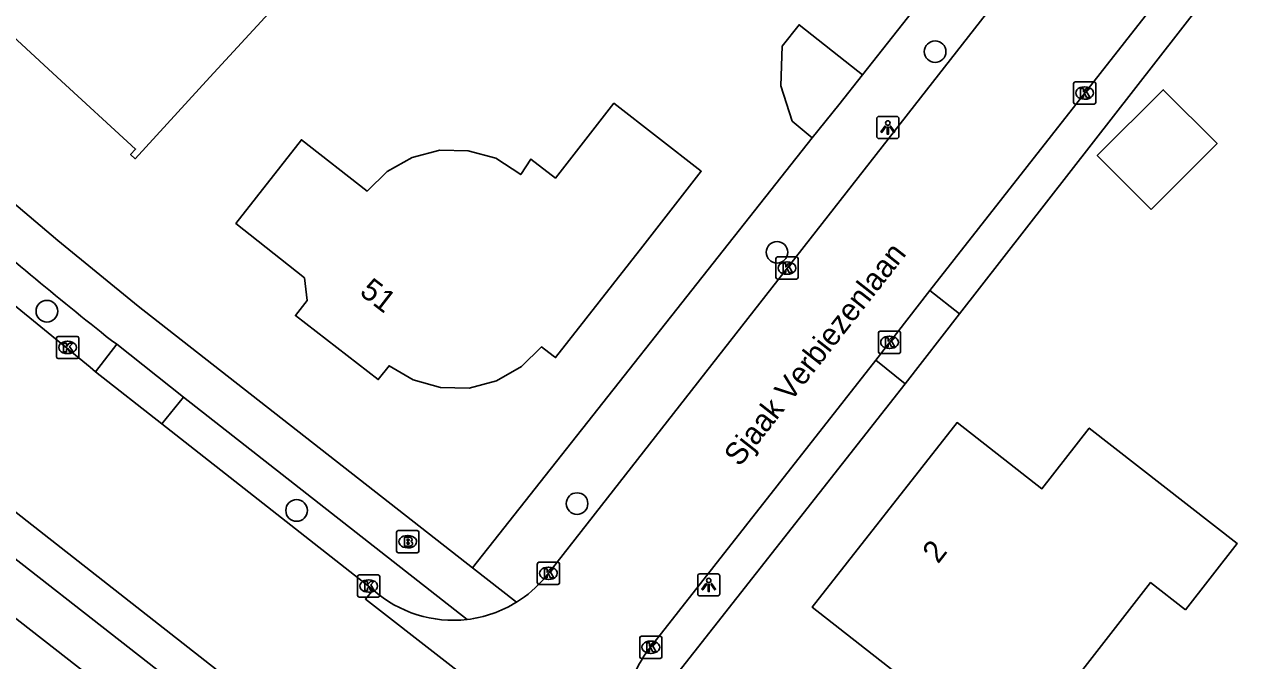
# Model space of a CAD drawing. Extents: x 157321 to 158827, y 386650 to 388532.
# Drawn here: x 158051 to 158106.5, y 387216.4 to 387245.2 of the extents above; entities that cross this region are included whole.
import ezdxf

# ---------------------------------------------------------------- set-up
doc = ezdxf.new("R2010")
doc.units = 0
for name, color, linetype in [('IMGEO_Boom', 7, 'Continuous'), ('IMGEO_Brandkraan', 7, 'Continuous'), ('IMGEO_Groenvoorziening', 7, 'Continuous'), ('IMGEO_Kolk', 7, 'Continuous'), ('IMGEO_Lichtpunt', 7, 'Continuous'), ('IMGEO_Openbare_ruimte_label', 7, 'Continuous'), ('IMGEO_Pand', 7, 'Continuous'), ('IMGEO_Pand_nummerreeks', 7, 'Continuous'), ('IMGEO_Rijbaan_lokaal_gesloten', 7, 'Continuous'), ('IMGEO_Voetpad_open', 7, 'Continuous')]:
    doc.layers.add(name, color=color, linetype=linetype)

msp = doc.modelspace()

# ---------------------------------------------------------------- linework, layer by layer
at = {"layer": 'IMGEO_Boom'}
for centre in [(158092.082, 387243.962), (158084.941, 387234.894), (158051.968, 387232.233), (158063.245, 387223.227), (158075.91, 387223.537)]:
    msp.add_circle(centre, 0.489, dxfattribs=at)
at = {"layer": 'IMGEO_Brandkraan'}
for p, q in [((158067.763, 387221.39), (158067.763, 387222.242)), ((158067.838, 387222.316), (158068.69, 387222.316)), ((158068.251, 387222.096), (158068.276, 387222.096)), ((158068.764, 387222.242), (158068.764, 387221.39)), ((158068.274, 387221.536), (158068.249, 387221.536)), ((158068.69, 387221.316), (158067.838, 387221.316))]:
    msp.add_line(p, q, dxfattribs=at)
for points in [[(158067.763, 387221.39), (158067.763, 387222.242)], [(158067.838, 387222.316), (158068.69, 387222.316)], [(158068.111, 387222.016), (158068.111, 387221.616), (158068.324, 387221.616)], [(158068.342, 387222.016), (158068.111, 387222.016)], [(158068.29, 387221.935), (158068.236, 387221.935), (158068.236, 387221.859)], [(158068.764, 387222.242), (158068.764, 387221.39)], [(158068.236, 387221.859), (158068.289, 387221.859)], [(158068.298, 387221.783), (158068.236, 387221.783), (158068.236, 387221.702)], [(158068.236, 387221.702), (158068.298, 387221.702)], [(158068.69, 387221.316), (158067.838, 387221.316)]]:
    msp.add_lwpolyline(points, dxfattribs=at)
for centre, radius, start, end in [((158067.84, 387222.24), 0.0765, 91.552, 178.448), ((158067.84, 387222.24), 0.0765, 91.552, 178.448), ((158068.291, 387221.897), 0.0379, 267.8285, 90.9355), ((158068.346, 387221.871), 0.145, 59.4692, 91.5367), ((158068.371, 387221.918), 0.0922, 285.5137, 58.1501), ((158068.688, 387222.24), 0.0765, 1.552, 88.448), ((158068.688, 387222.24), 0.0765, 1.552, 88.448), ((158067.84, 387221.392), 0.0765, 181.552, 268.448), ((158067.84, 387221.392), 0.0765, 181.552, 268.448), ((158068.299, 387221.742), 0.0404, 269.8759, 90.5077), ((158068.33, 387221.867), 0.251, 268.6676, 293.5347), ((158068.376, 387221.726), 0.105, 301.3115, 78.989), ((158068.688, 387221.392), 0.0765, 271.552, 358.448), ((158068.688, 387221.392), 0.0765, 271.552, 358.448)]:
    msp.add_arc(centre, radius, start, end, dxfattribs=at)
for centre, major_axis, ratio, start_param, end_param in [((158068.25, 387221.816), (-0.387, 0.002), 0.722429, 4.712389, 7.853982), ((158068.275, 387221.816), (-0.39, 0.002), 0.717154, 1.570796, 4.712389)]:
    msp.add_ellipse(centre, major_axis=major_axis, ratio=ratio, start_param=start_param, end_param=end_param, dxfattribs=at)
at = {"layer": 'IMGEO_Groenvoorziening'}
for points in [[(158088.804, 387242.909), (158103.97, 387262.173)], [(158112.253, 387256.634), (158107.095, 387250), (158093.185, 387232.11)], [(158071.192, 387220.632), (158086.535, 387240.062)], [(158090.73, 387228.956), (158079.248, 387214.335)]]:
    msp.add_lwpolyline(points, dxfattribs=at)
at = {"layer": 'IMGEO_Kolk'}
for p, q in [((158098.333, 387241.667), (158098.333, 387242.519)), ((158098.408, 387242.593), (158099.26, 387242.593)), ((158099.334, 387242.519), (158099.334, 387241.667)), ((158098.821, 387242.373), (158098.846, 387242.373)), ((158099.26, 387241.593), (158098.408, 387241.593)), ((158098.844, 387241.813), (158098.819, 387241.813)), ((158084.967, 387234.683), (158085.819, 387234.683)), ((158084.892, 387233.757), (158084.892, 387234.609)), ((158085.38, 387234.463), (158085.405, 387234.463)), ((158085.893, 387234.609), (158085.893, 387233.757)), ((158085.819, 387233.683), (158084.967, 387233.683)), ((158085.403, 387233.903), (158085.378, 387233.903)), ((158089.599, 387231.326), (158090.451, 387231.326)), ((158052.401, 387230.168), (158052.401, 387231.02)), ((158052.476, 387231.094), (158053.328, 387231.094)), ((158052.889, 387230.874), (158052.914, 387230.874)), ((158053.402, 387231.02), (158053.402, 387230.168)), ((158089.524, 387230.4), (158089.524, 387231.252)), ((158090.012, 387231.106), (158090.037, 387231.106)), ((158090.525, 387231.252), (158090.525, 387230.4)), ((158052.912, 387230.314), (158052.887, 387230.314)), ((158090.451, 387230.326), (158089.599, 387230.326)), ((158090.035, 387230.546), (158090.01, 387230.546)), ((158053.328, 387230.094), (158052.476, 387230.094)), ((158074.116, 387219.96), (158074.116, 387220.812)), ((158074.191, 387220.886), (158075.043, 387220.886)), ((158075.117, 387220.812), (158075.117, 387219.96)), ((158066.001, 387219.387), (158066.001, 387220.239)), ((158066.076, 387220.313), (158066.928, 387220.313)), ((158067.002, 387220.239), (158067.002, 387219.387)), ((158074.604, 387220.666), (158074.629, 387220.666)), ((158066.489, 387220.093), (158066.514, 387220.093)), ((158075.043, 387219.886), (158074.191, 387219.886)), ((158074.627, 387220.106), (158074.602, 387220.106)), ((158066.928, 387219.313), (158066.076, 387219.313)), ((158066.512, 387219.533), (158066.487, 387219.533)), ((158078.74, 387216.618), (158078.74, 387217.47)), ((158078.815, 387217.544), (158079.667, 387217.544)), ((158079.741, 387217.47), (158079.741, 387216.618)), ((158079.228, 387217.324), (158079.253, 387217.324)), ((158079.667, 387216.544), (158078.815, 387216.544)), ((158079.251, 387216.764), (158079.226, 387216.764))]:
    msp.add_line(p, q, dxfattribs=at)
for points in [[(158098.333, 387241.667), (158098.333, 387242.519)], [(158098.408, 387242.593), (158099.26, 387242.593)], [(158099.334, 387242.519), (158099.334, 387241.667)], [(158098.654, 387242.293), (158098.777, 387242.293), (158098.777, 387242.142), (158098.907, 387242.293), (158099.071, 387242.293), (158098.925, 387242.142), (158099.078, 387241.893), (158098.926, 387241.893), (158098.841, 387242.057), (158098.777, 387241.99), (158098.777, 387241.893), (158098.654, 387241.893), (158098.654, 387242.293)], [(158099.26, 387241.593), (158098.408, 387241.593)], [(158084.967, 387234.683), (158085.819, 387234.683)], [(158084.892, 387233.757), (158084.892, 387234.609)], [(158085.213, 387234.383), (158085.336, 387234.383), (158085.336, 387234.232), (158085.466, 387234.383), (158085.63, 387234.383), (158085.484, 387234.232), (158085.637, 387233.983), (158085.485, 387233.983), (158085.4, 387234.147), (158085.336, 387234.08), (158085.336, 387233.983), (158085.213, 387233.983), (158085.213, 387234.383)], [(158085.893, 387234.609), (158085.893, 387233.757)], [(158085.819, 387233.683), (158084.967, 387233.683)], [(158089.599, 387231.326), (158090.451, 387231.326)], [(158052.401, 387230.168), (158052.401, 387231.02)], [(158052.476, 387231.094), (158053.328, 387231.094)], [(158052.722, 387230.794), (158052.845, 387230.794), (158052.845, 387230.643), (158052.975, 387230.794), (158053.139, 387230.794), (158052.993, 387230.643), (158053.146, 387230.394), (158052.994, 387230.394), (158052.909, 387230.558), (158052.845, 387230.491), (158052.845, 387230.394), (158052.722, 387230.394), (158052.722, 387230.794)], [(158053.402, 387231.02), (158053.402, 387230.168)], [(158089.524, 387230.4), (158089.524, 387231.252)], [(158089.845, 387231.026), (158089.968, 387231.026), (158089.968, 387230.875), (158090.098, 387231.026), (158090.262, 387231.026), (158090.116, 387230.875), (158090.269, 387230.626), (158090.117, 387230.626), (158090.032, 387230.79), (158089.968, 387230.723), (158089.968, 387230.626), (158089.845, 387230.626), (158089.845, 387231.026)], [(158090.525, 387231.252), (158090.525, 387230.4)], [(158090.451, 387230.326), (158089.599, 387230.326)], [(158053.328, 387230.094), (158052.476, 387230.094)], [(158074.116, 387219.96), (158074.116, 387220.812)], [(158074.191, 387220.886), (158075.043, 387220.886)], [(158075.117, 387220.812), (158075.117, 387219.96)], [(158066.001, 387219.387), (158066.001, 387220.239)], [(158066.076, 387220.313), (158066.928, 387220.313)], [(158067.002, 387220.239), (158067.002, 387219.387)], [(158074.437, 387220.586), (158074.56, 387220.586), (158074.56, 387220.435), (158074.69, 387220.586), (158074.854, 387220.586), (158074.708, 387220.435), (158074.861, 387220.186), (158074.709, 387220.186), (158074.624, 387220.35), (158074.56, 387220.283), (158074.56, 387220.186), (158074.437, 387220.186), (158074.437, 387220.586)], [(158066.322, 387220.013), (158066.445, 387220.013), (158066.445, 387219.862), (158066.575, 387220.013), (158066.739, 387220.013), (158066.593, 387219.862), (158066.746, 387219.613), (158066.594, 387219.613), (158066.509, 387219.777), (158066.445, 387219.71), (158066.445, 387219.613), (158066.322, 387219.613), (158066.322, 387220.013)], [(158075.043, 387219.886), (158074.191, 387219.886)], [(158066.928, 387219.313), (158066.076, 387219.313)], [(158078.74, 387216.618), (158078.74, 387217.47)], [(158078.815, 387217.544), (158079.667, 387217.544)], [(158079.741, 387217.47), (158079.741, 387216.618)], [(158079.061, 387217.244), (158079.184, 387217.244), (158079.184, 387217.093), (158079.314, 387217.244), (158079.478, 387217.244), (158079.332, 387217.093), (158079.485, 387216.844), (158079.333, 387216.844), (158079.248, 387217.008), (158079.184, 387216.941), (158079.184, 387216.844), (158079.061, 387216.844), (158079.061, 387217.244)], [(158079.667, 387216.544), (158078.815, 387216.544)]]:
    msp.add_lwpolyline(points, dxfattribs=at)
for centre, start, end in [((158098.41, 387242.517), 91.552, 178.448), ((158098.41, 387242.517), 91.552, 178.448), ((158099.258, 387242.517), 1.552, 88.448), ((158099.258, 387242.517), 1.552, 88.448), ((158098.41, 387241.669), 181.552, 268.448), ((158098.41, 387241.669), 181.552, 268.448), ((158099.258, 387241.669), 271.552, 358.448), ((158099.258, 387241.669), 271.552, 358.448), ((158084.969, 387234.607), 91.552, 178.448), ((158084.969, 387234.607), 91.552, 178.448), ((158085.817, 387234.607), 1.552, 88.448), ((158085.817, 387234.607), 1.552, 88.448), ((158084.969, 387233.759), 181.552, 268.448), ((158084.969, 387233.759), 181.552, 268.448), ((158085.817, 387233.759), 271.552, 358.448), ((158085.817, 387233.759), 271.552, 358.448), ((158089.601, 387231.25), 91.552, 178.448), ((158089.601, 387231.25), 91.552, 178.448), ((158090.449, 387231.25), 1.552, 88.448), ((158090.449, 387231.25), 1.552, 88.448), ((158052.478, 387231.018), 91.552, 178.448), ((158052.478, 387231.018), 91.552, 178.448), ((158053.326, 387231.018), 1.552, 88.448), ((158053.326, 387231.018), 1.552, 88.448), ((158089.601, 387230.402), 181.552, 268.448), ((158089.601, 387230.402), 181.552, 268.448), ((158090.449, 387230.402), 271.552, 358.448), ((158090.449, 387230.402), 271.552, 358.448), ((158052.478, 387230.17), 181.552, 268.448), ((158052.478, 387230.17), 181.552, 268.448), ((158053.326, 387230.17), 271.552, 358.448), ((158053.326, 387230.17), 271.552, 358.448), ((158074.193, 387220.81), 91.552, 178.448), ((158074.193, 387220.81), 91.552, 178.448), ((158075.041, 387220.81), 1.552, 88.448), ((158075.041, 387220.81), 1.552, 88.448), ((158066.078, 387220.237), 91.552, 178.448), ((158066.078, 387220.237), 91.552, 178.448), ((158066.926, 387220.237), 1.552, 88.448), ((158066.926, 387220.237), 1.552, 88.448), ((158074.193, 387219.962), 181.552, 268.448), ((158074.193, 387219.962), 181.552, 268.448), ((158075.041, 387219.962), 271.552, 358.448), ((158075.041, 387219.962), 271.552, 358.448), ((158066.078, 387219.389), 181.552, 268.448), ((158066.078, 387219.389), 181.552, 268.448), ((158066.926, 387219.389), 271.552, 358.448), ((158066.926, 387219.389), 271.552, 358.448), ((158078.817, 387217.468), 91.552, 178.448), ((158078.817, 387217.468), 91.552, 178.448), ((158079.665, 387217.468), 1.552, 88.448), ((158079.665, 387217.468), 1.552, 88.448), ((158078.817, 387216.62), 181.552, 268.448), ((158078.817, 387216.62), 181.552, 268.448), ((158079.665, 387216.62), 271.552, 358.448), ((158079.665, 387216.62), 271.552, 358.448)]:
    msp.add_arc(centre, 0.0765, start, end, dxfattribs=at)
for centre, major_axis, ratio, start_param, end_param in [((158098.82, 387242.093), (-0.387, 0.002), 0.722429, 4.712389, 7.853982), ((158098.845, 387242.093), (-0.39, 0.002), 0.717154, 1.570796, 4.712389), ((158085.379, 387234.183), (-0.387, 0.002), 0.722429, 4.712389, 7.853982), ((158085.404, 387234.183), (-0.39, 0.002), 0.717154, 1.570796, 4.712389), ((158052.888, 387230.594), (-0.387, 0.002), 0.722429, 4.712389, 7.853982), ((158052.913, 387230.594), (-0.39, 0.002), 0.717154, 1.570796, 4.712389), ((158090.011, 387230.826), (-0.387, 0.002), 0.722429, 4.712389, 7.853982), ((158090.036, 387230.826), (-0.39, 0.002), 0.717154, 1.570796, 4.712389), ((158074.603, 387220.386), (-0.387, 0.002), 0.722429, 4.712389, 7.853982), ((158074.628, 387220.386), (-0.39, 0.002), 0.717154, 1.570796, 4.712389), ((158066.488, 387219.813), (-0.387, 0.002), 0.722429, 4.712389, 7.853982), ((158066.513, 387219.813), (-0.39, 0.002), 0.717154, 1.570796, 4.712389), ((158079.227, 387217.044), (-0.387, 0.002), 0.722429, 4.712389, 7.853982), ((158079.252, 387217.044), (-0.39, 0.002), 0.717154, 1.570796, 4.712389)]:
    msp.add_ellipse(centre, major_axis=major_axis, ratio=ratio, start_param=start_param, end_param=end_param, dxfattribs=at)
at = {"layer": 'IMGEO_Lichtpunt'}
for p, q in [((158089.447, 387240.939), (158089.447, 387240.132)), ((158089.447, 387240.939), (158089.447, 387240.132)), ((158090.349, 387241.034), (158089.541, 387241.034)), ((158090.349, 387241.034), (158089.541, 387241.034)), ((158090.443, 387240.132), (158090.443, 387240.939)), ((158090.443, 387240.132), (158090.443, 387240.939)), ((158089.541, 387240.038), (158090.349, 387240.038)), ((158089.541, 387240.038), (158090.349, 387240.038)), ((158081.359, 387220.266), (158081.359, 387219.459)), ((158081.359, 387220.266), (158081.359, 387219.459)), ((158082.261, 387220.361), (158081.453, 387220.361)), ((158082.261, 387220.361), (158081.453, 387220.361)), ((158082.355, 387219.459), (158082.355, 387220.266)), ((158082.355, 387219.459), (158082.355, 387220.266)), ((158081.453, 387219.365), (158082.261, 387219.365)), ((158081.453, 387219.365), (158082.261, 387219.365))]:
    msp.add_line(p, q, dxfattribs=at)
for points in [[(158089.821, 387240.603), (158089.86, 387240.575), (158089.672, 387240.313), (158089.634, 387240.34), (158089.821, 387240.603)], [(158089.923, 387240.555), (158089.97, 387240.555), (158089.97, 387240.233), (158089.923, 387240.233), (158089.923, 387240.555)], [(158090.033, 387240.575), (158090.071, 387240.602), (158090.258, 387240.34), (158090.219, 387240.312), (158090.033, 387240.575)], [(158081.733, 387219.93), (158081.772, 387219.902), (158081.584, 387219.64), (158081.546, 387219.667), (158081.733, 387219.93)], [(158081.835, 387219.882), (158081.882, 387219.882), (158081.882, 387219.56), (158081.835, 387219.56), (158081.835, 387219.882)], [(158081.945, 387219.902), (158081.983, 387219.929), (158082.17, 387219.667), (158082.131, 387219.639), (158081.945, 387219.902)]]:
    msp.add_lwpolyline(points, dxfattribs=at)
for centre in [(158089.946, 387240.737), (158081.858, 387220.064)]:
    msp.add_circle(centre, 0.0994, dxfattribs=at)
for centre, start, end in [((158089.541, 387240.939), 90, 180), ((158089.541, 387240.939), 90, 180), ((158090.349, 387240.939), 0, 90), ((158090.349, 387240.939), 0, 90), ((158089.541, 387240.132), 180, 270), ((158089.541, 387240.132), 180, 270), ((158090.349, 387240.132), 270, 0), ((158090.349, 387240.132), 270, 360), ((158081.453, 387220.266), 90, 180), ((158081.453, 387220.266), 90, 180), ((158082.261, 387220.266), 0, 90), ((158082.261, 387220.266), 0, 90), ((158081.453, 387219.459), 180, 270), ((158081.453, 387219.459), 180, 270), ((158082.261, 387219.459), 270, 0), ((158082.261, 387219.459), 270, 360)]:
    msp.add_arc(centre, 0.0946, start, end, dxfattribs=at)
at = {"layer": 'IMGEO_Pand'}
for points in [[(158061.754, 387245.899), (158062.835, 387247.078), (158063.056, 387246.875), (158059.33, 387242.81), (158055.951, 387239.123), (158055.746, 387239.318), (158055.971, 387239.557), (158052.433, 387242.815), (158050.229, 387244.844), (158049.216, 387243.74), (158045.89, 387246.777), (158046.898, 387247.888), (158044.591, 387250), (158044.243, 387250.319), (158047.62, 387254.007), (158051.13, 387257.841), (158056.652, 387252.764), (158055.57, 387251.584), (158061.754, 387245.899)], [(158086.535, 387240.062), (158085.623, 387240.828), (158085.107, 387242.424), (158085.169, 387244.207), (158085.937, 387245.18), (158088.589, 387243.084), (158088.804, 387242.909)], [(158086.535, 387240.062), (158087.73, 387241.561), (158088.804, 387242.909)], [(158101.838, 387236.834), (158099.407, 387239.262), (158102.383, 387242.241), (158104.814, 387239.813), (158101.838, 387236.834)], [(158067.335, 387238.546), (158068.461, 387239.182), (158069.714, 387239.505), (158070.997, 387239.481), (158072.241, 387239.142), (158073.364, 387238.404), (158073.825, 387239.106), (158074.932, 387238.246), (158077.572, 387241.628), (158081.519, 387238.558), (158078.879, 387235.177), (158074.941, 387230.133), (158074.826, 387230.222), (158074.311, 387230.621), (158073.404, 387229.736), (158072.278, 387229.093), (158071.031, 387228.754), (158069.746, 387228.779), (158068.506, 387229.132), (158067.42, 387229.764), (158066.929, 387229.139), (158063.194, 387232.036), (158063.727, 387232.717), (158063.607, 387233.739), (158062.88, 387234.315), (158060.503, 387236.198), (158063.464, 387239.982), (158066.429, 387237.66), (158067.335, 387238.546)], [(158103.393, 387218.736), (158101.816, 387219.965), (158095.482, 387211.842), (158086.534, 387218.851), (158093.075, 387227.199), (158096.908, 387224.21), (158099.042, 387226.947), (158105.73, 387221.733), (158103.393, 387218.736)]]:
    msp.add_lwpolyline(points, dxfattribs=at)
at = {"layer": 'IMGEO_Rijbaan_lokaal_gesloten'}
for points in [[(158105.977, 387260.589), (158105.735, 387260.215), (158097.752, 387250), (158074.463, 387220.199)], [(158091.841, 387233.164), (158105.03, 387250), (158110.984, 387257.602)], [(158040.708, 387241.061), (158046.693, 387235.712), (158050.13, 387232.809), (158053.922, 387229.699), (158054.163, 387229.499)], [(158089.404, 387230.023), (158091.841, 387233.164)], [(158079.065, 387216.835), (158089.404, 387230.023)], [(158057.154, 387227.141), (158054.163, 387229.499)], [(158057.154, 387227.141), (158066.709, 387219.638)], [(158066.919, 387210.32), (158051.069, 387222.744)], [(158066.709, 387219.638), (158066.349, 387219.221), (158080.071, 387208.537), (158080.412, 387208.951)]]:
    msp.add_lwpolyline(points, dxfattribs=at)
for centre, radius, start, end in [((158206.491, 387419.752), 250.934, 229.11543, 231.72967), ((158070.318, 387223.669), 5.406, 301.9044, 320.063), ((158070.314, 387223.675), 5.412, 228.229, 276.6797), ((158070.319, 387223.662), 5.399, 276.6498, 301.9372), ((158083.605, 387213.559), 5.599, 144.1924, 163.7295)]:
    msp.add_arc(centre, radius, start, end, dxfattribs=at)
at = {"layer": 'IMGEO_Voetpad_open'}
for points in [[(158048.863, 387238.464), (158052.457, 387235.424), (158056.092, 387232.453), (158071.192, 387220.632)], [(158093.185, 387232.11), (158091.841, 387233.164)], [(158093.185, 387232.11), (158090.73, 387228.956)], [(158054.882, 387230.911), (158055.127, 387230.738)], [(158054.163, 387229.499), (158055.127, 387230.738)], [(158055.127, 387230.738), (158058.133, 387228.349)], [(158090.73, 387228.956), (158089.404, 387230.023)], [(158058.133, 387228.349), (158057.154, 387227.141)], [(158058.133, 387228.349), (158070.944, 387218.299)], [(158049.964, 387221.488), (158065.904, 387209.026)], [(158073.175, 387219.08), (158071.192, 387220.632)], [(158094.77, 387183.795), (158072.482, 387201.21), (158048.683, 387219.809)]]:
    msp.add_lwpolyline(points, dxfattribs=at)
msp.add_arc((158185.374, 387395.415), 209.976, 229.00506, 231.57684, dxfattribs=at)

# ---------------------------------------------------------------- texts
at = {"layer": 'IMGEO_Openbare_ruimte_label'}
msp.add_text('Sjaak Verbiezenlaan', height=1, rotation=51.9039, dxfattribs=at).set_placement((158083.254, 387225.166))
at = {"layer": 'IMGEO_Pand_nummerreeks'}
for s, rotation, p in [('51', 322.202, (158066.043, 387233.016)), ('2', 51.9198, (158092.215, 387220.784))]:
    msp.add_text(s, height=1, rotation=rotation, dxfattribs=at).set_placement(p)

doc.saveas('drawing.dxf')
